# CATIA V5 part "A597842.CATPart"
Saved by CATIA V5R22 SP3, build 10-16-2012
Part number: 527-502MEB
Revision: A
Definition: A597842
Nomenclature: BACKSHELL, RFI/EMI FOR EPXB CONNECTORS
Source: bought
Description: BACKSHELL, RFI/EMI FOR EPXB CONNECTORS
Publications: "BCP1", "BCP2", "BCP2 Direction", "BCP1 Direction", "Logical Termination.1", "BaCP", "BaCP_generated(BaCP)", "Coincidence_generated(BaCP)", "Orientation_generated(BaCP)", "Logical Pin.1"
Material "Density=.0500": density 1384 kg/m3
Bounding box of the stored display mesh (mm): x -43.863 to 43.863, y -1.295 to 44.704, z -9.144 to 9.144
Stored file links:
  C:\Users\u305772\OneDrive - Gulfstream Aerospace\AD PAG\Harness\A597842.CATPart
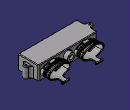
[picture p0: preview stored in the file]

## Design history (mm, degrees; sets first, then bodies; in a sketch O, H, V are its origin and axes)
Parameters
  PartNumber = "527-502MEB"
  OtherKeywords = "BACKSHELL, RFI/EMI FOR EPXB CONNECTORS"
  Comments = "EPXB BACKSHELL, THERMOPLASTIC, ELECTROLESS NICKEL PLATED"
  CAGECode = "06324"
  WeightComment = "CALCULATED FROM CATIA"
  WeightSource = "Calculated"
  Volume = 1.20949e-05 (volume) {= smartVolume(Body1)}
  Density = 1384 (density)
  Weight = 0.0369037 {= Volume*Density*2.20462262185}
Set1 "ConnectorGeometry"
  Point1 "BaCP": (0, 0, 0)
  Line1 "Orientation": type PtDir, RefPoint Point1, Direction (0, 0, 1), Start 0, End 12.7
  Line2 "Coincidence": type PtDir, RefPoint Point1, Direction (0, 1, 0), Start 0, End 12.7
  Point2: type OnPlane, Support end face of Pad5, RefPoint sketch element, H 0, V 0, Direction (-1, 0, 0)
  Point3: type OnPlane, Support end face of Pad5, RefPoint sketch element, H 0, V 0, Direction (-1, 0, 0)
  Line3: type PtDir, RefPoint Point3, Direction (0, 1, 0), Start 0, End 12.7
  Line4: type PtDir, RefPoint Point2, Direction (0, 1, 0), Start 0, End 12.7
Set2
  Plane1: type Offset, RefPlane xy-plane, Offset 1.5011
Body1 (main body)
  Sketch1 on xy-plane, origin (0, 0, 0), H (1, 0, 0), V (0, 1, 0)
    point P1 (0, 12.7)
    line L1 (37.6682, 25.4) -> (37.6682, 19.05)
    line L2 (37.6682, 0) -> (-37.6682, 0)
    line L3 (-37.6682, 0) -> (-37.6682, 6.35)
    line L4 (-37.6682, 25.4) -> (37.6682, 25.4)
    arc A1 centre (40.8432, 12.7) radius 3.175 from (40.8432, 9.525) to (40.8432, 15.875) ccw
    point P6 (40.8432, 12.7)
    arc A2 centre (40.8432, 19.05) radius 3.175 from (37.6682, 19.05) to (40.8432, 15.875) ccw
    arc A3 centre (40.8432, 6.35) radius 3.175 from (40.8432, 9.525) to (37.6682, 6.35) ccw
    point P9 (37.6682, 6.35)
    point P10 (40.8432, 9.525)
    point P11 (40.8432, 15.875)
    point P12 (37.6682, 19.05)
    line L5 (37.6682, 6.35) -> (37.6682, 0)
    point P13 (-40.8432, 15.875)
    point P14 (-37.6682, 19.05)
    arc A4 centre (-40.8432, 19.05) radius 3.175 from (-37.6682, 19.05) to (-40.8432, 15.875) cw
    point P16 (-40.8432, 9.525)
    arc A5 centre (-40.8432, 12.7) radius 3.175 from (-40.8432, 9.525) to (-40.8432, 15.875) cw
    point P18 (-37.6682, 6.35)
    arc A6 centre (-40.8432, 6.35) radius 3.175 from (-40.8432, 9.525) to (-37.6682, 6.35) cw
    line L6 (-37.6682, 19.05) -> (-37.6682, 25.4)
    circle A7 centre (40.8432, 12.7) radius 1.1303
    circle A8 centre (-40.8432, 12.7) radius 1.1303
    distance L4 L2 = 25.4
    distance L3 L1 = 75.3364
    distance P6 L4 = 12.7
    radius A1 = 3.175
    radius A2 = 3.175
    radius A3 = 3.175
    distance P12 L4 = 6.35
    radius A7 = 1.1303
    coincidence: P1 V, L2 H, L1 P9, L1 L5, L3 L6
    vertical: L1 V, L3 V, L5 V, L6 V
    horizontal: L2 H, L4 H
    equidistance: L1 L3 P1, L2 L4 P1
    tangency: A2 L1, A3 L1, A1 A2, A1 A3
    symmetry: P11 P13 V, P12 P14 V, A2 A4 V, P10 P16 V, A1 A5 V, P9 P18 V, A3 A6 V, A7 A8 V
  Pad1: profile Sketch1, direction (0, 0, 1), length 9.144, mirrored extent
  Sketch2 on xy-plane, origin (0, 0, 0), H (1, 0, 0), V (0, 1, 0)
    point P1 (-21.4503, 12.6492)
    line L1 (-7.0612, 21.844) -> (-7.0612, 3.4544)
    line L2 (-8.636, 1.8796) -> (-34.2646, 1.8796)
    line L3 (-35.8394, 3.4544) -> (-35.8394, 21.844)
    line L4 (-34.2646, 23.4188) -> (-8.636, 23.4188)
    reference intersected line E1 (-37.6682, 19.05) -> (-37.6682, 25.4) from face of Pad1 from Sketch1.L6
    reference intersected line E2 (37.6682, 0) -> (-37.6682, 0) from face of Pad1 from Sketch1.L2
    arc A1 centre (-8.636, 21.844) radius 1.5748 from (-7.0612, 21.844) to (-8.636, 23.4188) ccw
    point P2 (-7.0612, 21.844)
    point P3 (-8.636, 23.4188)
    arc A2 centre (-8.636, 3.4544) radius 1.5748 from (-7.0612, 3.4544) to (-8.636, 1.8796) cw
    point P5 (-7.0612, 3.4544)
    point P6 (-8.636, 1.8796)
    arc A3 centre (-34.2646, 3.4544) radius 1.5748 from (-34.2646, 1.8796) to (-35.8394, 3.4544) cw
    point P8 (-34.2646, 1.8796)
    point P9 (-35.8394, 3.4544)
    arc A4 centre (-34.2646, 21.844) radius 1.5748 from (-35.8394, 21.844) to (-34.2646, 23.4188) cw
    point P11 (-35.8394, 21.844)
    point P12 (-34.2646, 23.4188)
    point P14 (21.4503, 12.6492)
    point P15 (7.0612, 21.844)
    point P16 (8.636, 23.4188)
    point P18 (7.0612, 3.4544)
    point P19 (8.636, 1.8796)
    point P21 (34.2646, 1.8796)
    point P22 (35.8394, 3.4544)
    point P24 (35.8394, 21.844)
    point P25 (34.2646, 23.4188)
    line L5 (7.0612, 21.844) -> (7.0612, 3.4544)
    line L6 (8.636, 1.8796) -> (34.2646, 1.8796)
    line L7 (35.8394, 3.4544) -> (35.8394, 21.844)
    line L8 (34.2646, 23.4188) -> (8.636, 23.4188)
    arc A5 centre (8.636, 21.844) radius 1.5748 from (7.0612, 21.844) to (8.636, 23.4188) cw
    arc A6 centre (8.636, 3.4544) radius 1.5748 from (7.0612, 3.4544) to (8.636, 1.8796) ccw
    arc A7 centre (34.2646, 3.4544) radius 1.5748 from (34.2646, 1.8796) to (35.8394, 3.4544) ccw
    arc A8 centre (34.2646, 21.844) radius 1.5748 from (35.8394, 21.844) to (34.2646, 23.4188) ccw
    point P27 (0, 8.4074)
    construction line L9 (5.6134, 17.272) -> (5.6134, -2.032)
    construction line L10 (5.6134, -2.032) -> (-5.6134, -2.032)
    construction line L11 (-5.6134, -2.032) -> (-5.6134, 17.272)
    construction line L12 (-4.0386, 18.8468) -> (4.0386, 18.8468)
    construction arc A9 centre (4.0386, 17.272) radius 1.5748 from (5.6134, 17.272) to (4.0386, 18.8468) ccw
    construction arc A10 centre (-4.0386, 17.272) radius 1.5748 from (-5.6134, 17.272) to (-4.0386, 18.8468) cw
    reference projected line E3 (-37.6682, 0) -> (37.6682, 0) from edge [face of Pad1 from Sketch1.L2 | end face of Pad1]
    reference projected line E4 (-37.6682, 0) -> (37.6682, 0) from edge [face of Pad1 from Sketch1.L2 | end face of Pad1]
    distance L4 L2 = 21.5392
    distance L3 L1 = 28.7782
    distance L3 E1 = 1.8288
    distance L2 E2 = 1.8796
    radius A1 = 1.5748
    radius A2 = 1.5748 {= Sketch2.radius(A1)}
    radius A3 = 1.5748 {= Sketch2.radius(A1)}
    radius A4 = 1.5748 {= Sketch2.radius(A1)}
    radius A9 = 1.5748
    radius A10 = 1.5748 {= Sketch2.radius(A9)}
    distance L12 E3 = 18.8468
    distance L11 L9 = 11.2268
    distance E4 L10 = 2.032
    vertical: L1 V, L3 V, L9 V, L11 V
    horizontal: L2 H, L4 H, L10 H, L12 H
    equidistance: L1 L3 P1, L2 L4 P1, L9 L11 P27, L10 L12 P27
    tangency: A1 L1, A1 L4, A2 L1, A2 L2, A3 L2, A3 L3, A4 L3, A4 L4, A9 L9, A9 L12, A10 L11, A10 L12
    symmetry: P1 P14 V, P2 P15 V, P3 P16 V, P5 P18 V, P6 P19 V, P8 P21 V, P9 P22 V, P11 P24 V, P12 P25 V, L1 L5 V, L2 L6 V, L3 L7 V, L4 L8 V, A1 A5 V, A2 A6 V, A3 A7 V, A4 A8 V
    coincidence: P27 V
  Pocket1: profile Sketch2, direction (0, 0, -1), length 8.382, mirrored extent
  Sketch3 on face of Pad1 from Sketch1.L2, origin (0, 0, 0), H (1, 0, 0), V (0, 0, 1)
    point P1 (-20.9042, 0)
    line L1 (-7.0866, 4.1783) -> (-7.0866, -4.1783)
    line L2 (-8.2804, -5.3721) -> (-33.528, -5.3721)
    line L3 (-34.7218, -4.1783) -> (-34.7218, 4.1783)
    line L4 (-33.528, 5.3721) -> (-8.2804, 5.3721)
    reference intersected line E1 (-37.6682, -9.144) -> (-37.6682, 9.144) from face of Pad1 from Sketch1.L3
    arc A1 centre (-8.2804, 4.1783) radius 1.1938 from (-7.0866, 4.1783) to (-8.2804, 5.3721) ccw
    point P2 (-7.0866, 4.1783)
    point P3 (-8.2804, 5.3721)
    arc A2 centre (-8.2804, -4.1783) radius 1.1938 from (-7.0866, -4.1783) to (-8.2804, -5.3721) cw
    point P5 (-7.0866, -4.1783)
    point P6 (-8.2804, -5.3721)
    arc A3 centre (-33.528, -4.1783) radius 1.1938 from (-33.528, -5.3721) to (-34.7218, -4.1783) cw
    point P8 (-33.528, -5.3721)
    point P9 (-34.7218, -4.1783)
    arc A4 centre (-33.528, 4.1783) radius 1.1938 from (-34.7218, 4.1783) to (-33.528, 5.3721) cw
    point P11 (-34.7218, 4.1783)
    point P12 (-33.528, 5.3721)
    point P14 (20.9042, 0)
    point P15 (7.0866, 4.1783)
    point P16 (8.2804, 5.3721)
    point P18 (7.0866, -4.1783)
    point P19 (8.2804, -5.3721)
    point P21 (33.528, -5.3721)
    point P22 (34.7218, -4.1783)
    point P24 (34.7218, 4.1783)
    point P25 (33.528, 5.3721)
    line L5 (7.0866, 4.1783) -> (7.0866, -4.1783)
    line L6 (8.2804, -5.3721) -> (33.528, -5.3721)
    line L7 (34.7218, -4.1783) -> (34.7218, 4.1783)
    line L8 (33.528, 5.3721) -> (8.2804, 5.3721)
    arc A5 centre (8.2804, 4.1783) radius 1.1938 from (7.0866, 4.1783) to (8.2804, 5.3721) cw
    arc A6 centre (8.2804, -4.1783) radius 1.1938 from (7.0866, -4.1783) to (8.2804, -5.3721) ccw
    arc A7 centre (33.528, -4.1783) radius 1.1938 from (33.528, -5.3721) to (34.7218, -4.1783) ccw
    arc A8 centre (33.528, 4.1783) radius 1.1938 from (34.7218, 4.1783) to (33.528, 5.3721) ccw
    distance L3 L1 = 27.6352
    distance L3 E1 = 2.9464
    radius A1 = 1.1938
    radius A2 = 1.1938 {= Sketch3.radius(A1)}
    radius A3 = 1.1938 {= Sketch3.radius(A1)}
    radius A4 = 1.1938 {= Sketch3.radius(A1)}
    distance L4 L2 = 10.7442
    vertical: L1 V, L3 V
    horizontal: L2 H, L4 H
    equidistance: L1 L3 P1, L2 L4 P1
    tangency: A1 L1, A1 L4, A2 L1, A2 L2, A3 L2, A3 L3, A4 L3, A4 L4
    symmetry: P1 P14 V, P2 P15 V, P3 P16 V, P5 P18 V, P6 P19 V, P8 P21 V, P9 P22 V, P11 P24 V, P12 P25 V, L1 L5 V, L2 L6 V, L3 L7 V, L4 L8 V, A1 A5 V, A2 A6 V, A3 A7 V, A4 A8 V, L4 L2 H
  Pocket2: profile Sketch3, direction (0, 1, 0), length 8.382
  Sketch4 on face of Pad1 from Sketch1.L2, origin (0, 0, 0), H (1, 0, 0), V (0, 0, 1)
    point P1 (-20.9042, 0)
    line L1 (-7.0866, 4.1783) -> (-7.0866, -4.1783)
    line L2 (-8.2804, -5.3721) -> (-33.528, -5.3721)
    line L3 (-34.7218, -4.1783) -> (-34.7218, 4.1783)
    line L4 (-33.528, 5.3721) -> (-8.2804, 5.3721)
    reference intersected line E1 (-37.6682, -9.144) -> (-37.6682, 9.144) from face of Pad1 from Sketch1.L3
    arc A1 centre (-8.2804, 4.1783) radius 1.1938 from (-7.0866, 4.1783) to (-8.2804, 5.3721) ccw
    point P2 (-7.0866, 4.1783)
    point P3 (-8.2804, 5.3721)
    arc A2 centre (-8.2804, -4.1783) radius 1.1938 from (-7.0866, -4.1783) to (-8.2804, -5.3721) cw
    point P5 (-7.0866, -4.1783)
    point P6 (-8.2804, -5.3721)
    arc A3 centre (-33.528, -4.1783) radius 1.1938 from (-33.528, -5.3721) to (-34.7218, -4.1783) cw
    point P8 (-33.528, -5.3721)
    point P9 (-34.7218, -4.1783)
    arc A4 centre (-33.528, 4.1783) radius 1.1938 from (-34.7218, 4.1783) to (-33.528, 5.3721) cw
    point P11 (-34.7218, 4.1783)
    point P12 (-33.528, 5.3721)
    point P14 (20.9042, 0)
    point P15 (7.0866, 4.1783)
    point P16 (8.2804, 5.3721)
    point P18 (7.0866, -4.1783)
    point P19 (8.2804, -5.3721)
    point P21 (33.528, -5.3721)
    point P22 (34.7218, -4.1783)
    point P24 (34.7218, 4.1783)
    point P25 (33.528, 5.3721)
    line L5 (7.0866, 4.1783) -> (7.0866, -4.1783)
    line L6 (8.2804, -5.3721) -> (33.528, -5.3721)
    line L7 (34.7218, -4.1783) -> (34.7218, 4.1783)
    line L8 (33.528, 5.3721) -> (8.2804, 5.3721)
    arc A5 centre (8.2804, 4.1783) radius 1.1938 from (7.0866, 4.1783) to (8.2804, 5.3721) cw
    arc A6 centre (8.2804, -4.1783) radius 1.1938 from (7.0866, -4.1783) to (8.2804, -5.3721) ccw
    arc A7 centre (33.528, -4.1783) radius 1.1938 from (33.528, -5.3721) to (34.7218, -4.1783) ccw
    arc A8 centre (33.528, 4.1783) radius 1.1938 from (34.7218, 4.1783) to (33.528, 5.3721) ccw
    line L9 (-6.2992, 3.7973) -> (-6.2992, -3.7973)
    line L10 (-8.5344, -6.0325) -> (-33.274, -6.0325)
    line L11 (-35.5092, -3.7973) -> (-35.5092, 3.7973)
    line L12 (-33.274, 6.0325) -> (-8.5344, 6.0325)
    arc A9 centre (-8.5344, -3.7973) radius 2.2352 from (-6.2992, -3.7973) to (-8.5344, -6.0325) cw
    point P27 (-6.2992, -3.7973)
    point P28 (-8.5344, -6.0325)
    arc A10 centre (-8.5344, 3.7973) radius 2.2352 from (-6.2992, 3.7973) to (-8.5344, 6.0325) ccw
    point P30 (-6.2992, 3.7973)
    point P31 (-8.5344, 6.0325)
    arc A11 centre (-33.274, 3.7973) radius 2.2352 from (-35.5092, 3.7973) to (-33.274, 6.0325) cw
    point P33 (-35.5092, 3.7973)
    point P34 (-33.274, 6.0325)
    arc A12 centre (-33.274, -3.7973) radius 2.2352 from (-33.274, -6.0325) to (-35.5092, -3.7973) cw
    point P36 (-33.274, -6.0325)
    point P37 (-35.5092, -3.7973)
    point P39 (33.274, -6.0325)
    point P40 (8.5344, -6.0325)
    line L13 (8.5344, -6.0325) -> (33.274, -6.0325)
    point P41 (35.5092, -3.7973)
    arc A13 centre (33.274, -3.7973) radius 2.2352 from (33.274, -6.0325) to (35.5092, -3.7973) ccw
    point P43 (35.5092, 3.7973)
    line L14 (35.5092, -3.7973) -> (35.5092, 3.7973)
    point P44 (33.274, 6.0325)
    arc A14 centre (33.274, 3.7973) radius 2.2352 from (35.5092, 3.7973) to (33.274, 6.0325) ccw
    point P46 (8.5344, 6.0325)
    line L15 (33.274, 6.0325) -> (8.5344, 6.0325)
    point P47 (6.2992, 3.7973)
    arc A15 centre (8.5344, 3.7973) radius 2.2352 from (6.2992, 3.7973) to (8.5344, 6.0325) cw
    point P49 (6.2992, -3.7973)
    line L16 (6.2992, 3.7973) -> (6.2992, -3.7973)
    arc A16 centre (8.5344, -3.7973) radius 2.2352 from (6.2992, -3.7973) to (8.5344, -6.0325) ccw
    distance L3 L1 = 27.6352
    distance L3 E1 = 2.9464
    radius A1 = 1.1938
    radius A2 = 1.1938 {= Sketch4.radius(A1)}
    radius A3 = 1.1938 {= Sketch4.radius(A1)}
    radius A4 = 1.1938 {= Sketch4.radius(A1)}
    radius A9 = 2.2352
    radius A10 = 2.2352 {= Sketch4.radius(A9)}
    radius A11 = 2.2352 {= Sketch4.radius(A9)}
    radius A12 = 2.2352 {= Sketch4.radius(A9)}
    distance L12 L4 = 0.6604
    distance L11 L3 = 0.7874
    distance L12 L10 = 12.065
    vertical: L1 V, L3 V, L9 V, L11 V
    horizontal: L2 H, L4 H, L10 H, L12 H
    equidistance: L1 L3 P1, L2 L4 P1, L9 L11 P1, L10 L12 P1
    tangency: A1 L1, A1 L4, A2 L1, A2 L2, A3 L2, A3 L3, A4 L3, A4 L4, A9 L9, A9 L10, A10 L9, A10 L12, A11 L11, A11 L12, A12 L10, A12 L11
    symmetry: P1 P14 V, P2 P15 V, P3 P16 V, P5 P18 V, P6 P19 V, P8 P21 V, P9 P22 V, P11 P24 V, P12 P25 V, L1 L5 V, L2 L6 V, L3 L7 V, L4 L8 V, A1 A5 V, A2 A6 V, A3 A7 V, A4 A8 V, P36 P39 V, P28 P40 V, L10 L13 V, P37 P41 V, A12 A13 V, P33 P43 V, L11 L14 V, P34 P44 V, A11 A14 V, P31 P46 V, L12 L15 V, P30 P47 V, A10 A15 V, P27 P49 V, L9 L16 V, A9 A16 V, L12 L10 H
  Pad2: profile Sketch4, direction (0, -1, 0), length 1.2954
  Sketch5 on face of Pad1 from Sketch1.L2, origin (0, 0, 0), H (1, 0, 0), V (0, 0, 1)
    point P1 (42.4738, 12.319)
    line L1 (47.2794, 19.685) -> (47.2794, 4.953)
    line L2 (47.2794, 4.953) -> (37.6682, 4.953)
    line L3 (37.6682, 4.953) -> (37.6682, 19.685)
    line L4 (37.6682, 19.685) -> (47.2794, 19.685)
    reference projected line E1 (37.6682, -9.144) -> (37.6682, 9.144) from edge [face of Pad1 from Sketch1.L4 | face of Pad1 from Sketch1.L1]
    reference intersected line E2 (-37.6682, 9.144) -> (37.6682, 9.144) from end face of Pad1
    point P6 (-43.5102, -12.319)
    line L5 (-37.6682, -4.953) -> (-37.6682, -19.685)
    line L6 (-37.6682, -19.685) -> (-49.3522, -19.685)
    line L7 (-49.3522, -19.685) -> (-49.3522, -4.953)
    line L8 (-49.3522, -4.953) -> (-37.6682, -4.953)
    reference intersected line E3 (-37.6682, -9.144) -> (-37.6682, 9.144) from face of Pad1 from Sketch1.L3
    reference intersected line E4 (37.6682, -9.144) -> (-37.6682, -9.144) from start face of Pad1
    distance L2 L4 = 14.732
    distance L1 L3 = 9.6112
    distance L2 E2 = 4.191
    distance L8 L6 = 14.732
    distance L5 L7 = 11.684
    distance L8 E4 = 4.191
    vertical: L1 V, L3 V, L5 V, L7 V
    horizontal: L2 H, L4 H, L6 H, L8 H
    equidistance: L1 L3 P1, L2 L4 P1, L5 L7 P6, L6 L8 P6
    coincidence: L3 E1, L5 E3
  Pocket3: profile Sketch5, direction (0, 1, 0), length 25.4
  Sketch6 on xy-plane, origin (0, 0, 0), H (1, 0, 0), V (0, 1, 0)
    point P1 (0, 8.4074)
    line L1 (5.6134, 17.272) -> (5.6134, -2.032)
    line L2 (5.6134, -2.032) -> (-5.6134, -2.032)
    line L3 (-5.6134, -2.032) -> (-5.6134, 17.272)
    line L4 (-4.0386, 18.8468) -> (4.0386, 18.8468)
    arc A1 centre (4.0386, 17.272) radius 1.5748 from (5.6134, 17.272) to (4.0386, 18.8468) ccw
    arc A2 centre (-4.0386, 17.272) radius 1.5748 from (-5.6134, 17.272) to (-4.0386, 18.8468) cw
    reference projected line E1 (-37.6682, 0) -> (37.6682, 0) from edge [face of Pad1 from Sketch1.L2 | end face of Pad1]
    reference projected line E2 (-37.6682, 0) -> (37.6682, 0) from edge [face of Pad1 from Sketch1.L2 | end face of Pad1]
    radius A1 = 1.5748
    radius A2 = 1.5748 {= Sketch6.radius(A1)}
    distance L4 E1 = 18.8468
    distance L3 L1 = 11.2268
    distance E2 L2 = 2.032
    coincidence: P1 V
    vertical: L1 V, L3 V
    horizontal: L2 H, L4 H
    equidistance: L1 L3 P1, L2 L4 P1
    tangency: A1 L1, A1 L4, A2 L3, A2 L4
  Pocket4: profile Sketch6, direction (0, 0, -1), length 8.382, mirrored extent
  Sketch7 on face of Pad1 from Sketch1.L4, origin (0, 25.4, 0), H (-1, 0, 0), V (0, 0, 1)
    construction line L1 (0, -1.4986) -> (0, 1.4986)
    point P1 (0, -1.4986)
    point P2 (0, 1.4986)
    line L2 (-5.3848, -1.4986) -> (-5.3848, 1.4986)
    line L3 (5.3848, 1.4986) -> (5.3848, -1.4986)
    arc A1 centre (0, 1.4986) radius 5.3848 from (-5.3848, 1.4986) to (5.3848, 1.4986) cw
    arc A2 centre (0, -1.4986) radius 5.3848 from (5.3848, -1.4986) to (-5.3848, -1.4986) cw
    radius A1 = 5.3848
    distance A1 A2 = 13.7668
    coincidence: P1 V
    vertical: L1 V, L3 V
    tangency: A1 L2, A2 L2, A1 L3, A2 L3
    symmetry: P2 P1 H
  Pocket5: profile Sketch7, direction (0, -1, 0), length 4.572
  Sketch8 on end face of Pocket5, origin (0, 20.828, 0), H (-1, 0, 0), V (0, 0, 1)
    construction line L1 (0, 1.4986) -> (0, -1.4986)
    point P1 (0, 1.4986)
    line L2 (3.429, 1.4986) -> (3.429, -1.4986)
    line L3 (-3.429, -1.4986) -> (-3.429, 1.4986)
    arc A1 centre (0, -1.4986) radius 3.429 from (3.429, -1.4986) to (-3.429, -1.4986) cw
    arc A2 centre (0, 1.4986) radius 3.429 from (-3.429, 1.4986) to (3.429, 1.4986) cw
    distance L2 L3 = 6.858
    distance A2 A1 = 9.8552
    coincidence: P1 V
    vertical: L1 V
    tangency: A1 L2, A2 L2, A1 L3, A2 L3
    symmetry: A2 A1 H
  Pocket6: profile Sketch8, direction (0, -1, 0), length 4.572
  Sketch9 on face of Pad1 from Sketch1.L4, origin (0, 25.4, 0), H (-1, 0, 0), V (0, 0, 1)
    arc A1 centre (-21.5265, -14.3419) radius 20.5649 from (-10.4708, 2.9984) to (-32.5822, 2.9984) ccw
    point P1 (-21.5265, -14.3419)
    arc A2 centre (-21.5265, 14.3419) radius 20.5649 from (-32.5822, -2.9984) to (-10.4708, -2.9984) ccw
    point P2 (-21.5265, 14.3419)
    arc A3 centre (-12.3825, 0) radius 3.556 from (-10.4708, 2.9984) to (-10.4708, -2.9984) cw
    point P3 (-10.4708, 2.9984)
    point P4 (-10.4708, -2.9984)
    point P5 (-12.3825, 0)
    arc A4 centre (-30.6705, 0) radius 3.556 from (-32.5822, 2.9984) to (-32.5822, -2.9984) ccw
    point P6 (-32.5822, 2.9984)
    point P7 (-32.5822, -2.9984)
    point P8 (-30.6705, 0)
    construction line L1 (-30.6705, 0) -> (-12.3825, 0)
    construction line L2 (-21.5265, -14.3419) -> (-21.5265, 14.3419)
    reference projected line E1 (-5.3848, 1.4986) -> (-5.3848, -1.4986) from edge [face of Pad1 from Sketch1.L4 | face of Pocket5 from Sketch7.L2]
    reference projected line E2 (-37.6682, 9.144) -> (-37.6682, -9.144) from edge [face of Pocket3 | face of Pad1 from Sketch1.L4]
    point P9 (10.4708, -2.9984)
    point P10 (32.5822, -2.9984)
    arc A5 centre (21.5265, 14.3419) radius 20.5649 from (32.5822, -2.9984) to (10.4708, -2.9984) cw
    point P12 (32.5822, 2.9984)
    point P13 (10.4708, 2.9984)
    arc A6 centre (21.5265, -14.3419) radius 20.5649 from (10.4708, 2.9984) to (32.5822, 2.9984) cw
    arc A7 centre (30.6705, 0) radius 3.556 from (32.5822, 2.9984) to (32.5822, -2.9984) cw
    arc A8 centre (12.3825, 0) radius 3.556 from (10.4708, 2.9984) to (10.4708, -2.9984) ccw
    distance A1 A2 = 12.446
    distance A3 A4 = 25.4
    radius A3 = 3.556
    tangency: A3 A1, A3 A2, A4 A1, A4 A2
    vertical: L2 V
    horizontal: L1 H
    symmetry: P2 P1 H, P5 P8 L2, E1 E2 L2, P4 P9 V, P7 P10 V, A2 A5 V, P6 P12 V, P3 P13 V, A1 A6 V, A4 A7 V, A3 A8 V
    coincidence: L1 H
  Pocket7: profile Sketch9, direction (0, -1, 0), length 4.572
  Sketch10 on face of Pad1 from Sketch1.L4, origin (0, 25.4, 0), H (-1, 0, 0), V (0, 0, 1)
    arc A1 centre (-21.5265, -14.3419) radius 20.5649 from (-10.4708, 2.9984) to (-32.5822, 2.9984) ccw
    point P1 (-21.5265, -14.3419)
    arc A2 centre (-21.5265, 14.3419) radius 20.5649 from (-32.5822, -2.9984) to (-10.4708, -2.9984) ccw
    point P2 (-21.5265, 14.3419)
    arc A3 centre (-12.3825, 0) radius 3.556 from (-10.4708, 2.9984) to (-10.4708, -2.9984) cw
    point P3 (-10.4708, 2.9984)
    point P4 (-10.4708, -2.9984)
    point P5 (-12.3825, 0)
    arc A4 centre (-30.6705, 0) radius 3.556 from (-32.5822, 2.9984) to (-32.5822, -2.9984) ccw
    point P6 (-32.5822, 2.9984)
    point P7 (-32.5822, -2.9984)
    point P8 (-30.6705, 0)
    construction line L1 (-30.6705, 0) -> (-12.3825, 0)
    construction line L2 (-21.5265, -14.3419) -> (-21.5265, 14.3419)
    reference projected line E1 (-5.3848, 1.4986) -> (-5.3848, -1.4986) from edge [face of Pad1 from Sketch1.L4 | face of Pocket5 from Sketch7.L2]
    reference projected line E2 (-37.6682, 9.144) -> (-37.6682, -9.144) from edge [face of Pocket3 | face of Pad1 from Sketch1.L4]
    point P9 (10.4708, -2.9984)
    point P10 (32.5822, -2.9984)
    arc A5 centre (21.5265, 14.3419) radius 20.5649 from (32.5822, -2.9984) to (10.4708, -2.9984) cw
    point P12 (32.5822, 2.9984)
    point P13 (10.4708, 2.9984)
    arc A6 centre (21.5265, -14.3419) radius 20.5649 from (10.4708, 2.9984) to (32.5822, 2.9984) cw
    arc A7 centre (30.6705, 0) radius 3.556 from (32.5822, 2.9984) to (32.5822, -2.9984) cw
    arc A8 centre (12.3825, 0) radius 3.556 from (10.4708, 2.9984) to (10.4708, -2.9984) ccw
    arc A9 centre (30.6705, 0) radius 4.572 from (33.1284, -3.8551) to (33.1284, 3.8551) ccw
    point P17 (33.1284, -3.8551)
    point P18 (33.1284, 3.8551)
    arc A10 centre (21.5265, -14.3419) radius 21.5809 from (33.1284, 3.8551) to (9.9246, 3.8551) ccw
    point P19 (9.9246, 3.8551)
    arc A11 centre (12.3825, 0) radius 4.572 from (9.9246, 3.8551) to (9.9246, -3.8551) ccw
    point P20 (9.9246, -3.8551)
    arc A12 centre (21.5265, 14.3419) radius 21.5809 from (9.9246, -3.8551) to (33.1284, -3.8551) ccw
    point P21 (-33.1284, -3.8551)
    point P22 (-9.9246, -3.8551)
    arc A13 centre (-21.5265, 14.3419) radius 21.5809 from (-9.9246, -3.8551) to (-33.1284, -3.8551) cw
    point P23 (-9.9246, 3.8551)
    arc A14 centre (-12.3825, 0) radius 4.572 from (-9.9246, 3.8551) to (-9.9246, -3.8551) cw
    point P24 (-33.1284, 3.8551)
    arc A15 centre (-21.5265, -14.3419) radius 21.5809 from (-33.1284, 3.8551) to (-9.9246, 3.8551) cw
    arc A16 centre (-30.6705, 0) radius 4.572 from (-33.1284, -3.8551) to (-33.1284, 3.8551) cw
    point P25 (8.8265, 0)
    point P26 (-34.2265, 0)
    point P27 (-21.5265, 0)
    point P28 (21.5265, 0)
    distance A1 A2 = 12.446
    distance A3 A4 = 25.4
    radius A3 = 3.556
    distance A5 A12 = 1.016
    tangency: A3 A1, A3 A2, A4 A1, A4 A2, A10 A9, A9 A12, A12 A11, A11 A10
    vertical: L2 V
    horizontal: L1 H
    symmetry: P2 P1 H, P5 P8 L2, E1 E2 L2, P4 P9 V, P7 P10 V, A2 A5 V, P6 P12 V, P3 P13 V, A1 A6 V, A4 A7 V, A3 A8 V, P17 P21 V, P20 P22 V, A12 A13 V, P19 P23 V, A11 A14 V, P18 P24 V, A10 A15 V, A9 A16 V, P27 P28 V
    coincidence: L1 H, P25 H, P25 A8, P26 A4, P26 L1
    concentricity: A9 A7, A10 A6, A5 A12, A8 A11
    midpoint: P27 L2
  Pad3: profile Sketch10, direction (0, 1, 0), length 11.176
  Sketch11 on xy-plane, origin (0, 0, 0), H (1, 0, 0), V (0, 1, 0)
    line L1 (-8.8265, 25.4) -> (-8.8265, 36.576)
    line L2 (-8.8265, 36.576) -> (-7.3787, 36.576)
    line L3 (-7.3787, 36.576) -> (-7.3787, 35.1282)
    line L4 (-7.3787, 35.1282) -> (-7.8105, 35.1282)
    point P5 (-7.8105, 35.1282)
    line L5 (-7.8105, 35.1282) -> (-7.8105, 33.1642)
    line L6 (-7.8105, 25.4) -> (-8.8265, 25.4)
    reference intersected line E1 (-37.6682, 25.4) -> (37.6682, 25.4) from face of Pad1 from Sketch1.L4
    reference intersected line E2 (35.2425, 36.576) -> (34.2265, 36.576) from end face of Pad3
    reference projected point E6 (-8.8265, 25.4) from sketch element
    arc A1 centre (-8.0137, 32.8419) radius 0.381 from (-7.8105, 32.5196) to (-7.8105, 33.1642) ccw
    arc A2 centre (-8.0137, 31.5719) radius 0.381 from (-7.8105, 31.2496) to (-7.8105, 31.8942) ccw
    arc A3 centre (-8.0137, 30.3019) radius 0.381 from (-7.8105, 29.9796) to (-7.8105, 30.6242) ccw
    arc A4 centre (-8.0137, 29.0319) radius 0.381 from (-7.8105, 28.7096) to (-7.8105, 29.3542) ccw
    point P11 (-7.8105, 29.3542)
    line L7 (-7.8105, 28.7096) -> (-7.8105, 25.4)
    point P12 (-7.8105, 28.7096)
    point P13 (-7.8105, 30.6242)
    line L8 (-7.8105, 29.9796) -> (-7.8105, 29.3542)
    point P14 (-7.8105, 29.9796)
    point P15 (-7.8105, 31.8942)
    line L9 (-7.8105, 31.2496) -> (-7.8105, 30.6242)
    point P16 (-7.8105, 31.2496)
    line L10 (-7.8105, 32.5196) -> (-7.8105, 31.8942)
    point P18 (-7.8105, 32.5196)
    distance L5 L1 = 1.016
    distance L2 P5 = 1.4478
    distance L3 L1 = 1.4478
    distance A1 L5 = 0.1778
    radius A1 = 0.381
    radius A2 = 0.381
    radius A3 = 0.381
    radius A4 = 0.381
    distance A2 L5 = 0.1778
    distance A3 L5 = 0.1778
    distance A4 L5 = 0.1778
    distance P12 L6 = 3.3096
    distance P11 P14 = 0.6254
    distance P13 P16 = 0.6254
    distance P15 P18 = 0.6254
    vertical: L1 V, L3 V, L5 V, L7 V, L8 V, L9 V, L10 V
    horizontal: L2 H, L4 H, L6 H
    coincidence: L6 E1, L2 E2, E6 L1, L5 L7, L5 L8, L5 L9, L5 L10
  Sketch12 on face of Pad1 from Sketch1.L4, origin (0, 25.4, 0), H (-1, 0, 0), V (0, 0, 1)
    construction arc A1 centre (-21.5265, -14.3419) radius 20.5649 from (-10.4708, 2.9984) to (-32.5822, 2.9984) ccw
    point P1 (-21.5265, -14.3419)
    construction arc A2 centre (-21.5265, 14.3419) radius 20.5649 from (-32.5822, -2.9984) to (-10.4708, -2.9984) ccw
    point P2 (-21.5265, 14.3419)
    construction arc A3 centre (-12.3825, 0) radius 3.556 from (-10.4708, 2.9984) to (-10.4708, -2.9984) cw
    point P3 (-10.4708, 2.9984)
    point P4 (-10.4708, -2.9984)
    point P5 (-12.3825, 0)
    construction arc A4 centre (-30.6705, 0) radius 3.556 from (-32.5822, 2.9984) to (-32.5822, -2.9984) ccw
    point P6 (-32.5822, 2.9984)
    point P7 (-32.5822, -2.9984)
    point P8 (-30.6705, 0)
    construction line L1 (-30.6705, 0) -> (-12.3825, 0)
    construction line L2 (-21.5265, -14.3419) -> (-21.5265, 14.3419)
    reference projected line E1 (-5.3848, 1.4986) -> (-5.3848, -1.4986) from edge [face of Pad1 from Sketch1.L4 | face of Pocket5 from Sketch7.L2]
    reference projected line E2 (-37.6682, 9.144) -> (-37.6682, -9.144) from edge [face of Pocket3 | face of Pad1 from Sketch1.L4]
    point P9 (10.4708, -2.9984)
    point P10 (32.5822, -2.9984)
    arc A5 centre (21.5265, 14.3419) radius 20.5649 from (32.5822, -2.9984) to (10.4708, -2.9984) cw
    point P12 (32.5822, 2.9984)
    point P13 (10.4708, 2.9984)
    arc A6 centre (21.5265, -14.3419) radius 20.5649 from (10.4708, 2.9984) to (32.5822, 2.9984) cw
    arc A7 centre (30.6705, 0) radius 3.556 from (32.5822, 2.9984) to (32.5822, -2.9984) cw
    arc A8 centre (12.3825, 0) radius 3.556 from (10.4708, 2.9984) to (10.4708, -2.9984) ccw
    distance A1 A2 = 12.446
    distance A3 A4 = 25.4
    radius A3 = 3.556
    tangency: A3 A1, A3 A2, A4 A1, A4 A2
    vertical: L2 V
    horizontal: L1 H
    symmetry: P2 P1 H, P5 P8 L2, E1 E2 L2, P4 P9 V, P7 P10 V, A2 A5 V, P6 P12 V, P3 P13 V, A1 A6 V, A4 A7 V, A3 A8 V
    coincidence: L1 H
  Rib1: profile Sketch11, centre curve Sketch12
  Sketch13 on xy-plane, origin (0, 0, 0), H (1, 0, 0), V (0, 1, 0)
    line L1 (34.2265, 25.4) -> (34.2265, 36.576)
    line L2 (34.2265, 36.576) -> (35.6743, 36.576)
    line L3 (35.6743, 36.576) -> (35.6743, 35.1282)
    line L4 (35.6743, 35.1282) -> (35.2425, 35.1282)
    point P5 (35.2425, 35.1282)
    line L5 (35.2425, 35.1282) -> (35.2425, 33.1642)
    line L6 (35.2425, 25.4) -> (34.2265, 25.4)
    reference intersected line E1 (35.2425, 36.576) -> (34.2265, 36.576) from end face of Pad3
    arc A1 centre (35.0393, 32.8419) radius 0.381 from (35.2425, 32.5196) to (35.2425, 33.1642) ccw
    arc A2 centre (35.0393, 31.5719) radius 0.381 from (35.2425, 31.2496) to (35.2425, 31.8942) ccw
    arc A3 centre (35.0393, 30.3019) radius 0.381 from (35.2425, 29.9796) to (35.2425, 30.6242) ccw
    arc A4 centre (35.0393, 29.0319) radius 0.381 from (35.2425, 28.7096) to (35.2425, 29.3542) ccw
    point P11 (35.2425, 29.3542)
    line L7 (35.2425, 28.7096) -> (35.2425, 25.4)
    point P12 (35.2425, 28.7096)
    point P13 (35.2425, 30.6242)
    line L8 (35.2425, 29.9796) -> (35.2425, 29.3542)
    point P14 (35.2425, 29.9796)
    point P15 (35.2425, 31.8942)
    line L9 (35.2425, 31.2496) -> (35.2425, 30.6242)
    point P16 (35.2425, 31.2496)
    line L10 (35.2425, 32.5196) -> (35.2425, 31.8942)
    point P18 (35.2425, 32.5196)
    reference intersected line E5 (-37.6682, 25.4) -> (37.6682, 25.4) from face of Pad1 from Sketch1.L4
    reference projected point E6 (34.2265, 25.4) from sketch element
    distance L5 L1 = 1.016
    distance L2 P5 = 1.4478
    distance L3 L1 = 1.4478
    distance A1 L5 = 0.1778
    radius A1 = 0.381
    radius A2 = 0.381
    radius A3 = 0.381
    radius A4 = 0.381
    distance A2 L5 = 0.1778
    distance A3 L5 = 0.1778
    distance A4 L5 = 0.1778
    distance P12 L6 = 3.3096
    distance P11 P14 = 0.6254
    distance P13 P16 = 0.6254
    distance P15 P18 = 0.6254
    vertical: L1 V, L3 V, L5 V, L7 V, L8 V, L9 V, L10 V
    horizontal: L2 H, L4 H, L6 H
    coincidence: L2 E1, L5 L7, L5 L8, L5 L9, L5 L10, L6 E5, E6 L1
  Sketch14 on face of Pad1 from Sketch1.L4, origin (0, 25.4, 0), H (-1, 0, 0), V (0, 0, 1)
    arc A1 centre (-21.5265, -14.3419) radius 20.5649 from (-10.4708, 2.9984) to (-32.5822, 2.9984) ccw
    point P1 (-21.5265, -14.3419)
    arc A2 centre (-21.5265, 14.3419) radius 20.5649 from (-32.5822, -2.9984) to (-10.4708, -2.9984) ccw
    point P2 (-21.5265, 14.3419)
    arc A3 centre (-12.3825, 0) radius 3.556 from (-10.4708, 2.9984) to (-10.4708, -2.9984) cw
    point P5 (-12.3825, 0)
    arc A4 centre (-30.6705, 0) radius 3.556 from (-32.5822, 2.9984) to (-32.5822, -2.9984) ccw
    point P8 (-30.6705, 0)
    construction line L1 (-30.6705, 0) -> (-12.3825, 0)
    construction line L2 (-21.5265, -14.3419) -> (-21.5265, 14.3419)
    reference projected line E1 (-5.3848, 1.4986) -> (-5.3848, -1.4986) from edge [face of Pad1 from Sketch1.L4 | face of Pocket5 from Sketch7.L2]
    reference projected line E2 (-37.6682, 9.144) -> (-37.6682, -9.144) from edge [face of Pocket3 | face of Pad1 from Sketch1.L4]
    distance A1 A2 = 12.446
    distance A3 A4 = 25.4
    radius A3 = 3.556
    tangency: A3 A1, A3 A2, A4 A1, A4 A2
    vertical: L2 V
    horizontal: L1 H
    symmetry: P2 P1 H, P5 P8 L2, E1 E2 L2
    coincidence: L1 H
  Rib2: profile Sketch13, centre curve Sketch14
  Sketch15 on face of Rib1, origin (0, 36.576, 0), H (-1, 0, 0), V (0, 0, 1)
    arc A1 centre (-21.5265, 14.3419) radius 20.5649 from (-24.7015, -5.9764) to (-18.3515, -5.9764) ccw
    arc A2 centre (-21.5265, 14.3419) radius 22.0127 from (-24.7015, -7.4406) to (-18.3515, -7.4406) ccw
    reference projected arc E1 centre (-21.5265, 14.3419) radius 20.5649 from (-32.1246, -3.2818) to (-10.9284, -3.2818) ccw from edge [face of Rib2 | face of Pad3]
    reference projected arc E2 centre (-21.5265, 14.3419) radius 22.0127 from (-32.8708, -4.5225) to (-10.1822, -4.5225) ccw from edge [face of Rib2 | face of Rib2]
    line L1 (-18.3515, -5.9764) -> (-18.3515, -7.4406)
    point P2 (-18.3515, -5.9764)
    point P3 (-18.3515, -7.4406)
    line L2 (-24.7015, -7.4406) -> (-24.7015, -5.9764)
    point P4 (-24.7015, -7.4406)
    point P5 (-24.7015, -5.9764)
    construction line L3 (-21.5265, 14.3419) -> (-21.5265, -6.223)
    point P6 (-21.5265, -6.223)
    point P7 (18.3515, -5.9764)
    point P8 (18.3515, -7.4406)
    point P9 (24.7015, -7.4406)
    point P10 (24.7015, -5.9764)
    point P11 (21.5265, -6.223)
    arc A3 centre (21.5265, 14.3419) radius 20.5649 from (24.7015, -5.9764) to (18.3515, -5.9764) cw
    arc A4 centre (21.5265, 14.3419) radius 22.0127 from (24.7015, -7.4406) to (18.3515, -7.4406) cw
    line L4 (18.3515, -5.9764) -> (18.3515, -7.4406)
    line L5 (24.7015, -7.4406) -> (24.7015, -5.9764)
    distance L1 L2 = 6.35
    coincidence: A1 E1, A2 E2, P6 A1
    vertical: L1 V, L2 V, L3 V
    symmetry: L1 L2 L3, P2 P7 V, P3 P8 V, P4 P9 V, P5 P10 V, P6 P11 V, A1 A3 V, A2 A4 V, L1 L4 V, L2 L5 V
  Pad4: profile Sketch15, direction (0, 1, 0), length 6.5532
  Sketch16 on end face of Pad4, origin (0, 43.1292, 0), H (-1, 0, 0), V (0, 0, 1)
    arc A1 centre (-21.5265, 14.3419) radius 20.5649 from (-26.289, -5.6639) to (-16.764, -5.6639) ccw
    reference projected arc E1 centre (-21.5265, 14.3419) radius 20.5649 from (-24.4672, -6.0117) to (-18.5858, -6.0117) ccw from edge [face of Pad4 from Sketch15.A1 | end face of Pad4]
    arc A2 centre (-21.5265, 14.3419) radius 22.7747 from (-26.289, -7.9293) to (-16.764, -7.9293) ccw
    point P2 (-21.5265, 14.3419)
    reference projected arc E2 centre (-21.5265, 14.3419) radius 22.0127 from (-24.4815, -7.4716) to (-18.5715, -7.4716) ccw from edge [face of Pad4 from Sketch15.A2 | end face of Pad4]
    line L1 (-16.764, -5.6639) -> (-16.764, -7.9293)
    point P3 (-16.764, -5.6639)
    point P4 (-16.764, -7.9293)
    line L2 (-26.289, -5.6639) -> (-26.289, -7.9293)
    point P5 (-26.289, -5.6639)
    point P6 (-26.289, -7.9293)
    construction line L3 (-21.5265, -6.223) -> (-21.5265, -8.4328)
    point P7 (-21.5265, -6.223)
    point P8 (-21.5265, -8.4328)
    point P9 (16.764, -5.6639)
    point P10 (16.764, -7.9293)
    point P11 (26.289, -5.6639)
    point P12 (26.289, -7.9293)
    point P13 (21.5265, -8.4328)
    point P14 (21.5265, -6.223)
    construction line L4 (21.5265, -6.223) -> (21.5265, -8.4328)
    arc A3 centre (21.5265, 14.3419) radius 20.5649 from (26.289, -5.6639) to (16.764, -5.6639) cw
    arc A4 centre (21.5265, 14.3419) radius 22.7747 from (26.289, -7.9293) to (16.764, -7.9293) cw
    line L5 (16.764, -5.6639) -> (16.764, -7.9293)
    line L6 (26.289, -5.6639) -> (26.289, -7.9293)
    distance A2 A1 = 2.2098
    distance L1 L2 = 9.525
    coincidence: A1 E1, P7 A1, P8 A2, L3 P2
    concentricity: A2 E2
    vertical: L1 V, L2 V, L3 V
    symmetry: L1 L2 L3, P3 P9 V, P4 P10 V, P5 P11 V, P6 P12 V, P8 P13 V, P7 P14 V, L3 L4 V, A1 A3 V, A2 A4 V, L1 L5 V, L2 L6 V
  Pad5: profile Sketch16, direction (0, 1, 0), length 1.5748
  Fillet1: radius 1.524, on edge [face of Pocket3 | face of Pad1 from Sketch1.L4] (x2)
  Fillet2: radius 0.762, on edge [face of Pad5 | end face of Pad5] (x2); edge [face of Pad1 from Sketch1.A2 | face of Pocket3 from Sketch5.L2]; edge [end face of Pad1 | face of Pocket3]; edge [start face of Pad1 | face of Pocket3]
  Fillet3: radius 1.2116, on edge [face of Rib2 | face of Pad4 from Sketch15.L2]; edge [face of Pad4 from Sketch15.L2 | start face of Pad5]; edge [face of Pad4 from Sketch15.L1 | start face of Pad5]; edge [face of Rib2 | face of Pad4 from Sketch15.L1]; edge [face of Rib1 | face of Pad4 from Sketch15.L5]; edge [face of Pad4 from Sketch15.L5 | start face of Pad5]; edge [face of Pad4 from Sketch15.L4 | start face of Pad5]; edge [face of Rib1 | face of Pad4 from Sketch15.L4]
  Fillet4: radius 0.508, on edge [face of Pad4 from Sketch15.L5 | face of Pad4]; edge [face of Pad5 | face of Pad4 from Sketch15.L5]; edge [face of Pad4 from Sketch15.L1 | face of Pad4]; edge [face of Pad5 | face of Pad4 from Sketch15.L1]; edge [face of Pad4 | start face of Pad5] (x2); edge [face of Pad5 from Sketch16.L6 | face of Pad5 from Sketch16.A4]; edge [face of Pad5 from Sketch16.A4 | face of Pad5 from Sketch16.L5]; edge [face of Pad5 from Sketch16.L1 | face of Pad5 from Sketch16.A2]; edge [face of Pad5 from Sketch16.A2 | face of Pad5 from Sketch16.L2]
  Fillet5: radius 0.508, on edge [face of Pad5 from Sketch16.L6 | face of Fillet4]; edge [face of Pad5 from Sketch16.L1 | face of Fillet4]; edge [face of Pad1 from Sketch1.L4 | face of Pocket5 from Sketch7.A2]
  Sketch17 on Plane1, origin (0, 0, 1.5011), H (1, 0, 0), V (0, 1, 0)
    line L1 (2.54, 29.6672) -> (4.7625, 29.6672)
    line L2 (4.7625, 29.6672) -> (4.7625, 24.13)
    line L3 (4.7625, 24.13) -> (3.175, 24.13)
    line L4 (3.175, 24.13) -> (3.175, 18.542)
    line L5 (3.175, 18.542) -> (4.7625, 18.542)
    point P5 (4.7625, 18.542)
    line L6 (4.7625, 18.542) -> (4.7625, 0)
    line L7 (4.7625, 0) -> (3.175, 0)
    point P7 (0, 0)
    axis line L8 (0, 17.526) -> (0, 27.1272)
    line L9 (2.54, 29.6672) -> (2.54, 27.1272)
    line L10 (2.54, 27.1272) -> (1.27, 27.1272)
    point P10 (0, 27.1272)
    line L11 (1.27, 17.526) -> (3.175, 17.526)
    line L12 (3.175, 17.526) -> (3.175, 0)
    point P13 (0, 17.526)
    line L13 (1.27, 17.526) -> (1.27, 27.1272)
    reference intersected line E1 (37.6682, 0) -> (-37.6682, 0) from face of Pad1 from Sketch1.L2
    distance L2 L8 = 4.7625
    distance L1 L3 = 5.5372
    distance L10 L1 = 2.54
    distance L9 L8 = 2.54
    distance L4 L8 = 3.175
    distance L5 L3 = 5.588
    distance L11 L7 = 17.526
    distance L12 L8 = 3.175
    distance L13 L8 = 1.27
    distance L5 L7 = 18.542
    horizontal: L1 H, L3 H, L5 H, L7 H, L10 H, L11 H
    vertical: L2 V, L4 V, L6 V, L8 V, L9 V, L12 V, L13 V
    coincidence: P5 L2, P7 V, P7 L7, P7 L8, P13 L11, P10 L10, L7 E1
  Shaft1: profile Sketch17, axis Sketch17.L8, angle 360
  Sketch18 on end face of Pad1, origin (0, 0, 9.144), H (1, 0, 0), V (0, 1, 0)
    construction line L1 (21.5265, 24.638) -> (21.5265, 43.942)
    point P1 (21.5265, 24.638)
    point P2 (21.5265, 43.942)
    reference projected line E1 through (21.5265, 0) direction (0, 1) from axis of face of Pad5
    reference projected line E2 (-36.1442, 24.638) -> (36.1442, 24.638) from edge [end face of Pad1 | face of Fillet2]
    reference projected line E3 (16.764, 43.942) -> (26.289, 43.942) from edge [face of Pad5 | face of Fillet2]
    construction line L2 (25.7175, 27.0548) -> (32.3215, 27.0548)
    line L3 (25.7175, 28.0708) -> (32.3215, 28.0708)
    line L4 (32.3215, 26.0388) -> (25.7175, 26.0388)
    arc A1 centre (32.3215, 27.0548) radius 1.016 from (32.3215, 28.0708) to (32.3215, 26.0388) cw
    arc A2 centre (25.7175, 27.0548) radius 1.016 from (25.7175, 26.0388) to (25.7175, 28.0708) cw
    point P5 (25.7175, 28.0708)
    point P6 (32.3215, 28.0708)
    point P7 (32.3215, 26.0388)
    point P8 (25.7175, 26.0388)
    reference projected line E4 (9.9246, 28.7096) -> (33.1284, 28.7096) from edge [face of Rib2 | face of Rib2]
    reference intersected line E5 (-37.6682, 25.4) -> (37.6682, 25.4) from face of Pad1 from Sketch1.L4
    point P9 (10.7315, 26.0388)
    point P10 (10.7315, 28.0708)
    arc A3 centre (10.7315, 27.0548) radius 1.016 from (10.7315, 28.0708) to (10.7315, 26.0388) ccw
    point P12 (17.3355, 28.0708)
    line L5 (17.3355, 28.0708) -> (10.7315, 28.0708)
    point P13 (17.3355, 26.0388)
    line L6 (10.7315, 26.0388) -> (17.3355, 26.0388)
    arc A4 centre (17.3355, 27.0548) radius 1.016 from (17.3355, 26.0388) to (17.3355, 28.0708) ccw
    construction line L7 (-25.7175, 27.0548) -> (-32.3215, 27.0548)
    point P17 (-25.7175, 28.0708)
    point P18 (-32.3215, 28.0708)
    point P19 (-32.3215, 26.0388)
    point P20 (-25.7175, 26.0388)
    point P21 (-10.7315, 26.0388)
    point P22 (-10.7315, 28.0708)
    point P24 (-17.3355, 28.0708)
    point P25 (-17.3355, 26.0388)
    line L8 (-25.7175, 28.0708) -> (-32.3215, 28.0708)
    line L9 (-32.3215, 26.0388) -> (-25.7175, 26.0388)
    arc A5 centre (-32.3215, 27.0548) radius 1.016 from (-32.3215, 28.0708) to (-32.3215, 26.0388) ccw
    arc A6 centre (-25.7175, 27.0548) radius 1.016 from (-25.7175, 26.0388) to (-25.7175, 28.0708) ccw
    arc A7 centre (-10.7315, 27.0548) radius 1.016 from (-10.7315, 28.0708) to (-10.7315, 26.0388) cw
    line L10 (-17.3355, 28.0708) -> (-10.7315, 28.0708)
    line L11 (-10.7315, 26.0388) -> (-17.3355, 26.0388)
    arc A8 centre (-17.3355, 27.0548) radius 1.016 from (-17.3355, 26.0388) to (-17.3355, 28.0708) cw
    distance L4 L3 = 2.032
    distance A1 A2 = 8.636
    distance A2 A4 = 6.35
    vertical: L1 V
    coincidence: L1 E1, P1 E2, P2 E3
    horizontal: L2 H
    tangency: A1 L3, A2 L3, A1 L4, A2 L4
    symmetry: E4 E5 L2, P7 P9 L1, P6 P10 L1, A1 A3 L1, P5 P12 L1, L3 L5 L1, P8 P13 L1, L4 L6 L1, A2 A4 L1, L2 L7 V, P5 P17 V, P6 P18 V, P7 P19 V, P8 P20 V, P9 P21 V, P10 P22 V, P12 P24 V, P13 P25 V, L3 L8 V, L4 L9 V, A1 A5 V, A2 A6 V, A3 A7 V, L5 L10 V, L6 L11 V, A4 A8 V
  Pocket8: profile Sketch18, direction (0, 0, -1), length 26.9748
